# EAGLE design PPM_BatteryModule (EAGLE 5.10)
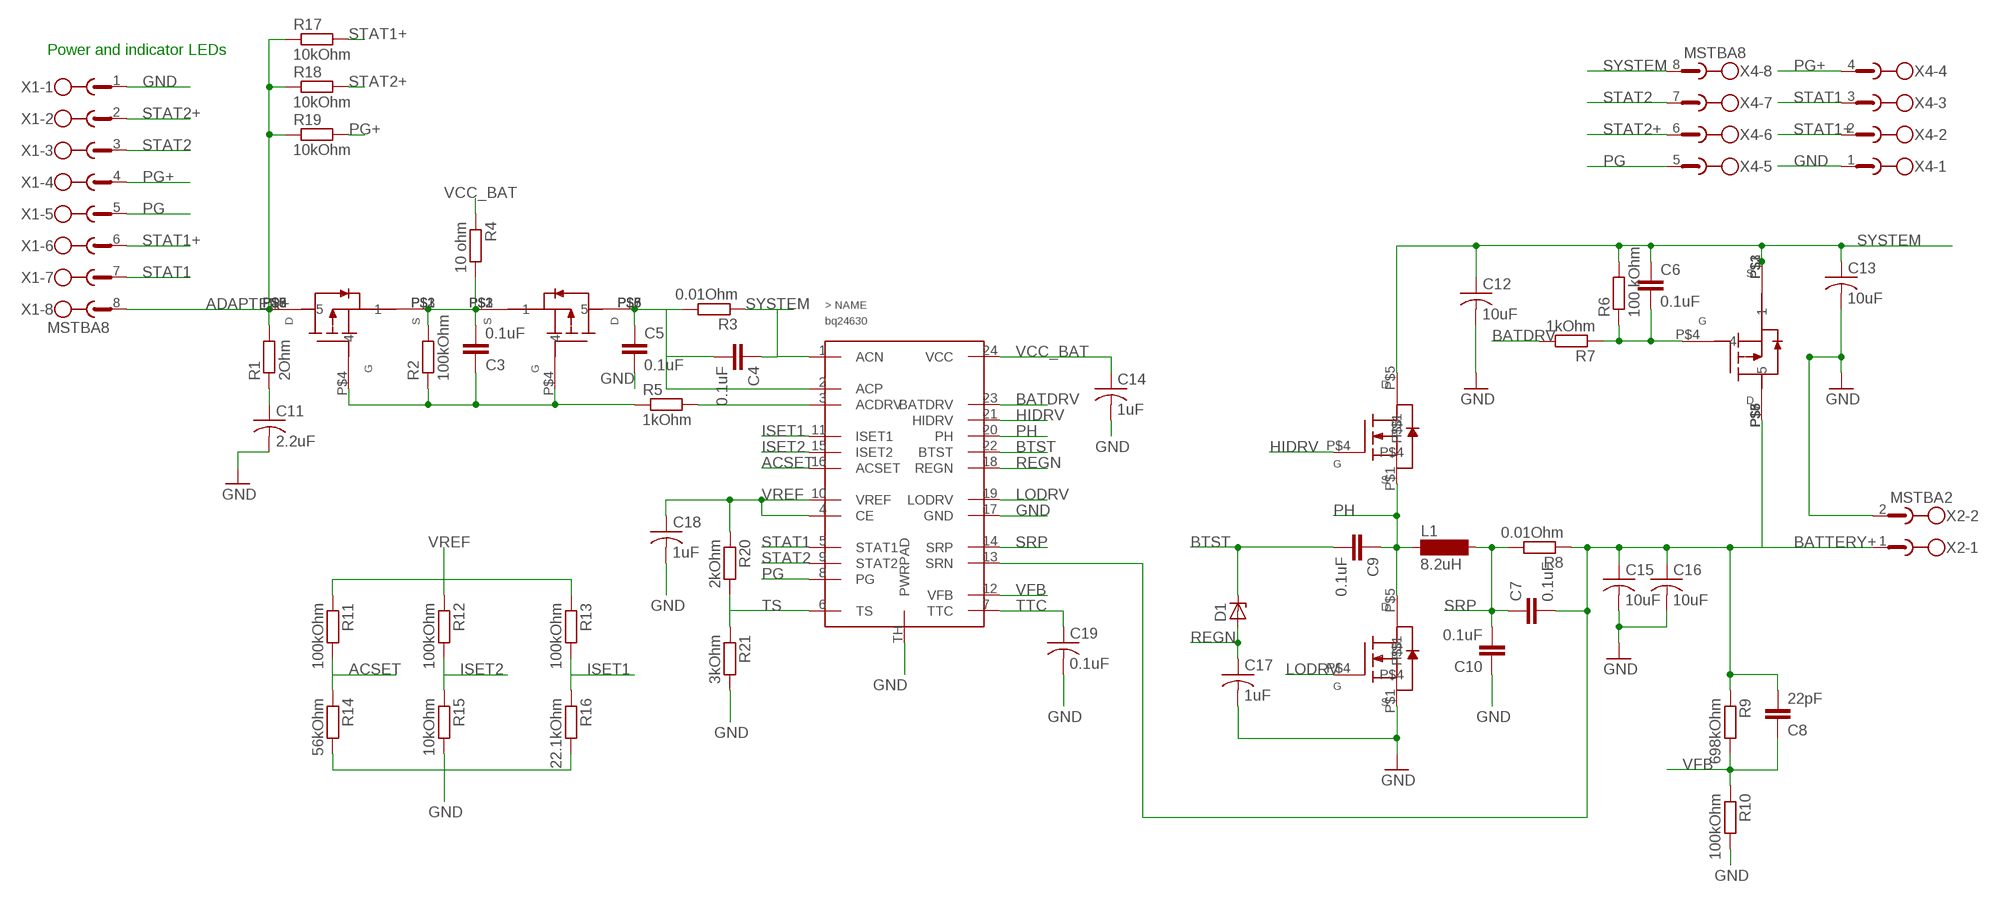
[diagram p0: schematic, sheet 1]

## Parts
C3  0.1uF  C-EUC1206  [C1206]
C4  0.1uF  C-EUC1206  [C1206]
C5  0.1uF  C-EUC1206  [C1206]
C6  0.1uF  C-EUC1206  [C1206]
C7  0.1uF  C-EUC1206  [C1206]
C8  22pF  C-EUC1206  [C1206]
C9  0.1uF  C-EUC1206  [C1206]
C10  0.1uF  C-EUC1206  [C1206]
C11  2.2uF  C-USC1206  [C1206]
C12  10uF  C-USC1206  [C1206]
C13  10uF  C-USC1206  [C1206]
C14  1uF  C-USC1206  [C1206]
C15  10uF  C-USC1206  [C1206]
C16  10uF  C-USC1206  [C1206]
C17  1uF  C-USC1206  [C1206]
C18  1uF  C-USC1206  [C1206]
C19  0.1uF  C-USC1206  [C1206]
D1  ZENER-DIODESOD80C  [SOD80C]
L1  8.2uH  SM-1206  [SM-1206]
Q1  SI7617DN  [POWERPAK1212-8]
Q2  SI7617DN  [POWERPAK1212-8]
Q3  SI7617DN  [POWERPAK1212-8]
Q4  SIS412DN  [POWERPAK1212-8]
Q5  SIS412DN  [POWERPAK1212-8]
R1  2Ohm  R-EU_M1206  [M1206]
R2  100kOhm  R-EU_M1206  [M1206]
R3  0.01Ohm  R-EU_M1206  [M1206]
R4  10 ohm  R-EU_M1206  [M1206]
R5  1kOhm  R-EU_M1206  [M1206]
R6  100 kOhm  R-EU_M1206  [M1206]
R7  1kOhm  R-EU_M1206  [M1206]
R8  0.01Ohm  R-EU_M1206  [M1206]
R9  698kOhm  R-EU_M1206  [M1206]
R10  100kOhm  R-EU_M1206  [M1206]
R11  100kOhm  R-EU_M1206  [M1206]
R12  100kOhm  R-EU_M1206  [M1206]
R13  100kOhm  R-EU_M1206  [M1206]
R14  56kOhm  R-EU_M1206  [M1206]
R15  10kOhm  R-EU_M1206  [M1206]
R16  22.1kOhm  R-EU_M1206  [M1206]
R17  10kOhm  R-EU_M1206  [M1206]
R18  10kOhm  R-EU_M1206  [M1206]
R19  10kOhm  R-EU_M1206  [M1206]
R20  2kOhm  R-EU_M1206  [M1206]
R21  3kOhm  R-EU_M1206  [M1206]
U$1  BQ24630  [QFN16]
X1  MSTBA8  [MSTBA8]
X2  MSTBA2  [MSTBA2]
X4  MSTBA8  [MSTBA8]

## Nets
ACP: C4.2 C5.1 Q2.P$5 Q2.P$6 Q2.P$7 Q2.P$8 R3.2 U$1.2(ACP)
ACSET: R11.2 R14.1 U$1.16(ACSET)
ADAPTER+: Q1.P$5 Q1.P$6 Q1.P$7 Q1.P$8 R1.2 R17.1 R18.1 R19.1 X1.8
BATDRV: R7.2 U$1.23(BATDRV)
BATTERY+: C7.2 C8.2 C15.1 C16.1 Q3.P$5 R8.1 R9.1 U$1.13(SRN) X2.1
BTST: C9.2 D1.C U$1.22(BTST)
GND: C5.2 C10.1 C11.2 C12.2 C13.2 C14.2 C15.2 C16.2 C17.2 C18.2 C19.2 Q5.P$1 R10.2 R14.2 R15.2 R16.2 R21.2 U$1.17(GND) U$1.TH(PWRPAD) X1.1 X2.2 X4.1
HIDRV: Q4.P$4 U$1.21(HIDRV)
ISET1: R13.2 R16.1 U$1.11(ISET1)
ISET2: R12.2 R15.1 U$1.15(ISET2)
LODRV: Q5.P$4 U$1.19(LODRV)
N$2: C3.2 Q1.P$1 Q1.P$2 Q1.P$3 Q2.P$1 Q2.P$2 Q2.P$3 R2.2 R4.2
N$6: C11.1 R1.1
N$7: C3.1 Q1.P$4 Q2.P$4 R2.1 R5.1
N$8: R5.2 U$1.3(ACDRV)
N$10: C6.2 Q3.P$4 R6.1 R7.1
PG: U$1.8(PG) X1.5 X4.5
PG+: R19.2 X1.4 X4.4
PH: C9.1 L1.1 Q4.P$1 Q5.P$5 U$1.20(PH)
REGN: C17.1 D1.A U$1.18(REGN)
SRP: C7.1 C10.2 L1.2 R8.2 U$1.14(SRP)
STAT1: U$1.5(STAT1) X1.7 X4.3
STAT1+: R17.2 X1.6 X4.2
STAT2: U$1.9(STAT2) X1.3 X4.7
STAT2+: R18.2 X1.2 X4.6
SYSTEM: C4.1 C6.1 C12.1 C13.1 Q3.P$1 Q3.P$2 Q3.P$3 Q4.P$5 R3.1 R6.2 U$1.1(ACN) X4.8
TS: R20.2 R21.1 U$1.6(TS)
TTC: C19.1 U$1.7(TTC)
VCC_BAT: C14.1 R4.1 U$1.24(VCC)
VFB: C8.1 R9.2 R10.1 U$1.12(VFB)
VREF: C18.1 R11.1 R12.1 R13.1 R20.1 U$1.4(CE) U$1.10(VREF)
Unconnected: Q3.P$6 Q3.P$7 Q3.P$8 Q4.P$2 Q4.P$3 Q4.P$6 Q4.P$7 Q4.P$8 Q5.P$2 Q5.P$3 Q5.P$6 Q5.P$7 Q5.P$8

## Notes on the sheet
- Power and indicator LEDs

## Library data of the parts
C3-C10 = rcl:C-EU: CAPACITOR, European symbol
C11-C19 = rcl:C-US: CAPACITOR, American symbol
D1 = diode:ZENER-DIODE: Z-Diode
L1 = inductor-neosid:SM-1206: INDUCTOR
Q1-Q3 = Oma:SI7617DN
Q4 Q5 = Oma:SIS412DN
R1-R21 = rcl:R-EU_: RESISTOR, European symbol
U$1 = Oma:BQ24630
X1 X4 = con-phoenix-508:MSTBA8: PHOENIX
X2 = con-phoenix-508:MSTBA2: PHOENIX

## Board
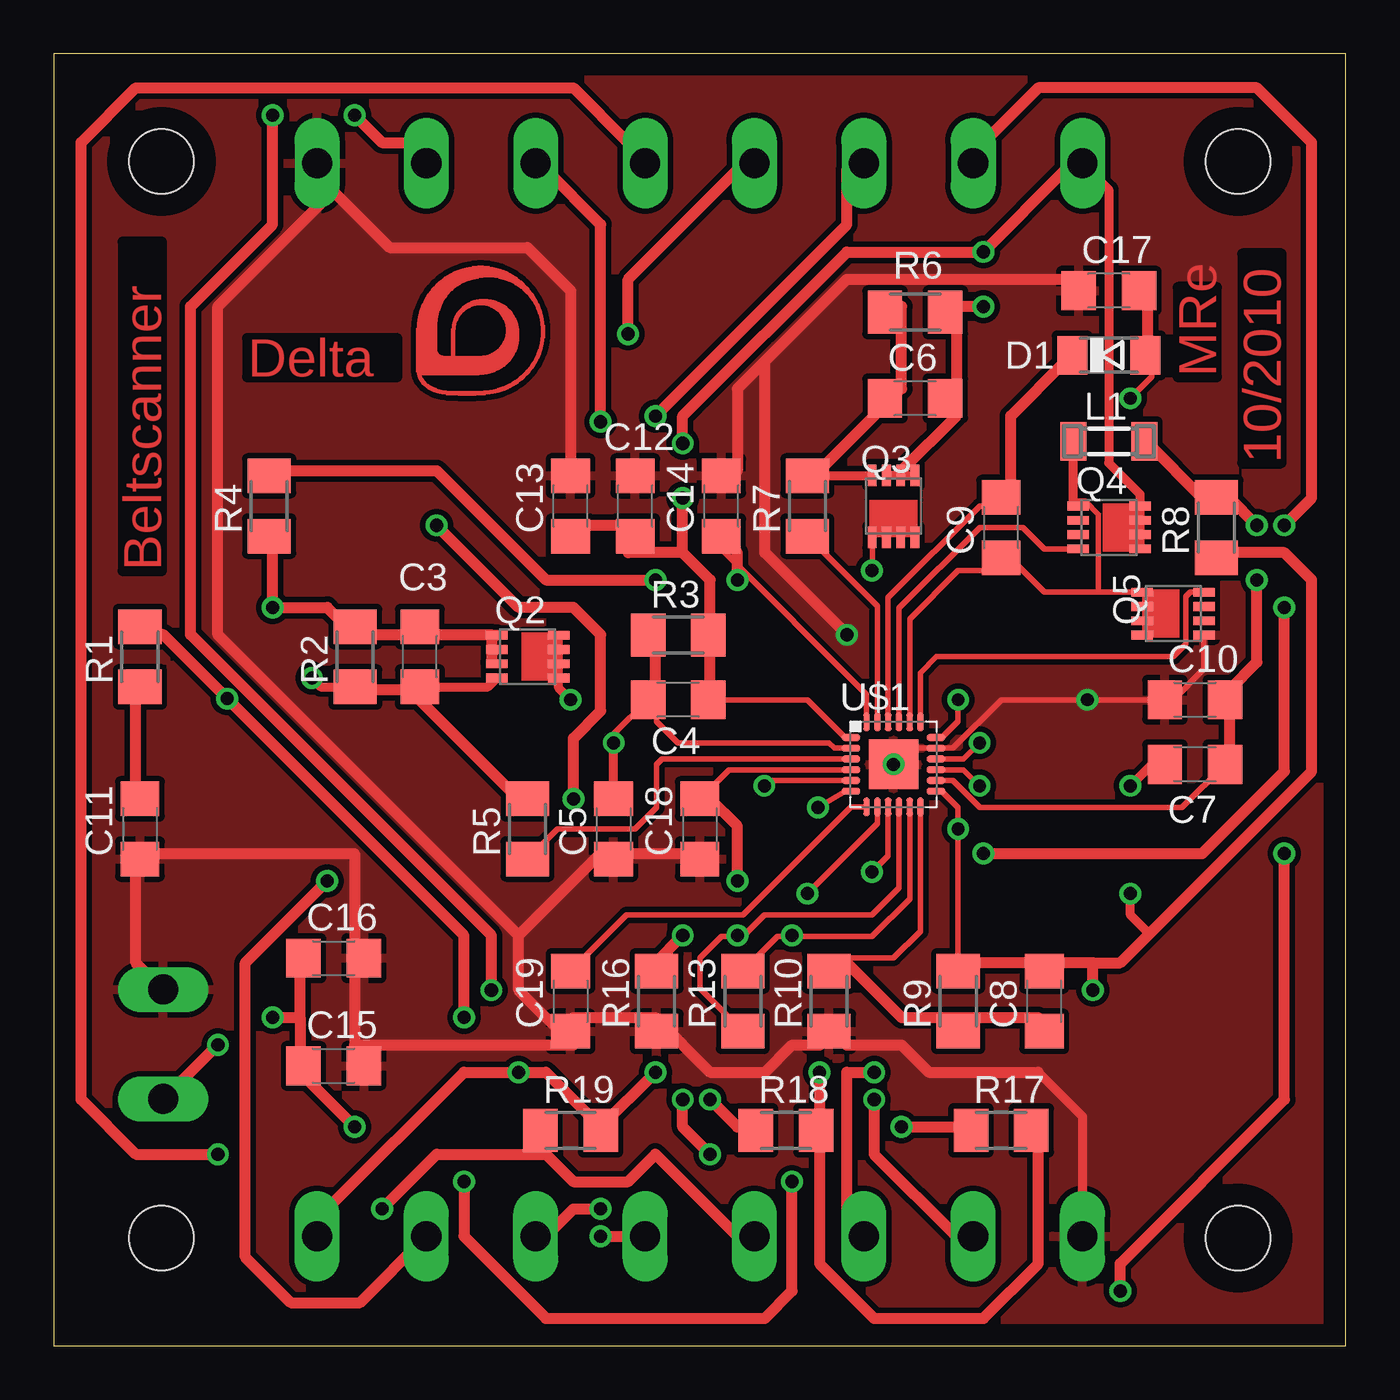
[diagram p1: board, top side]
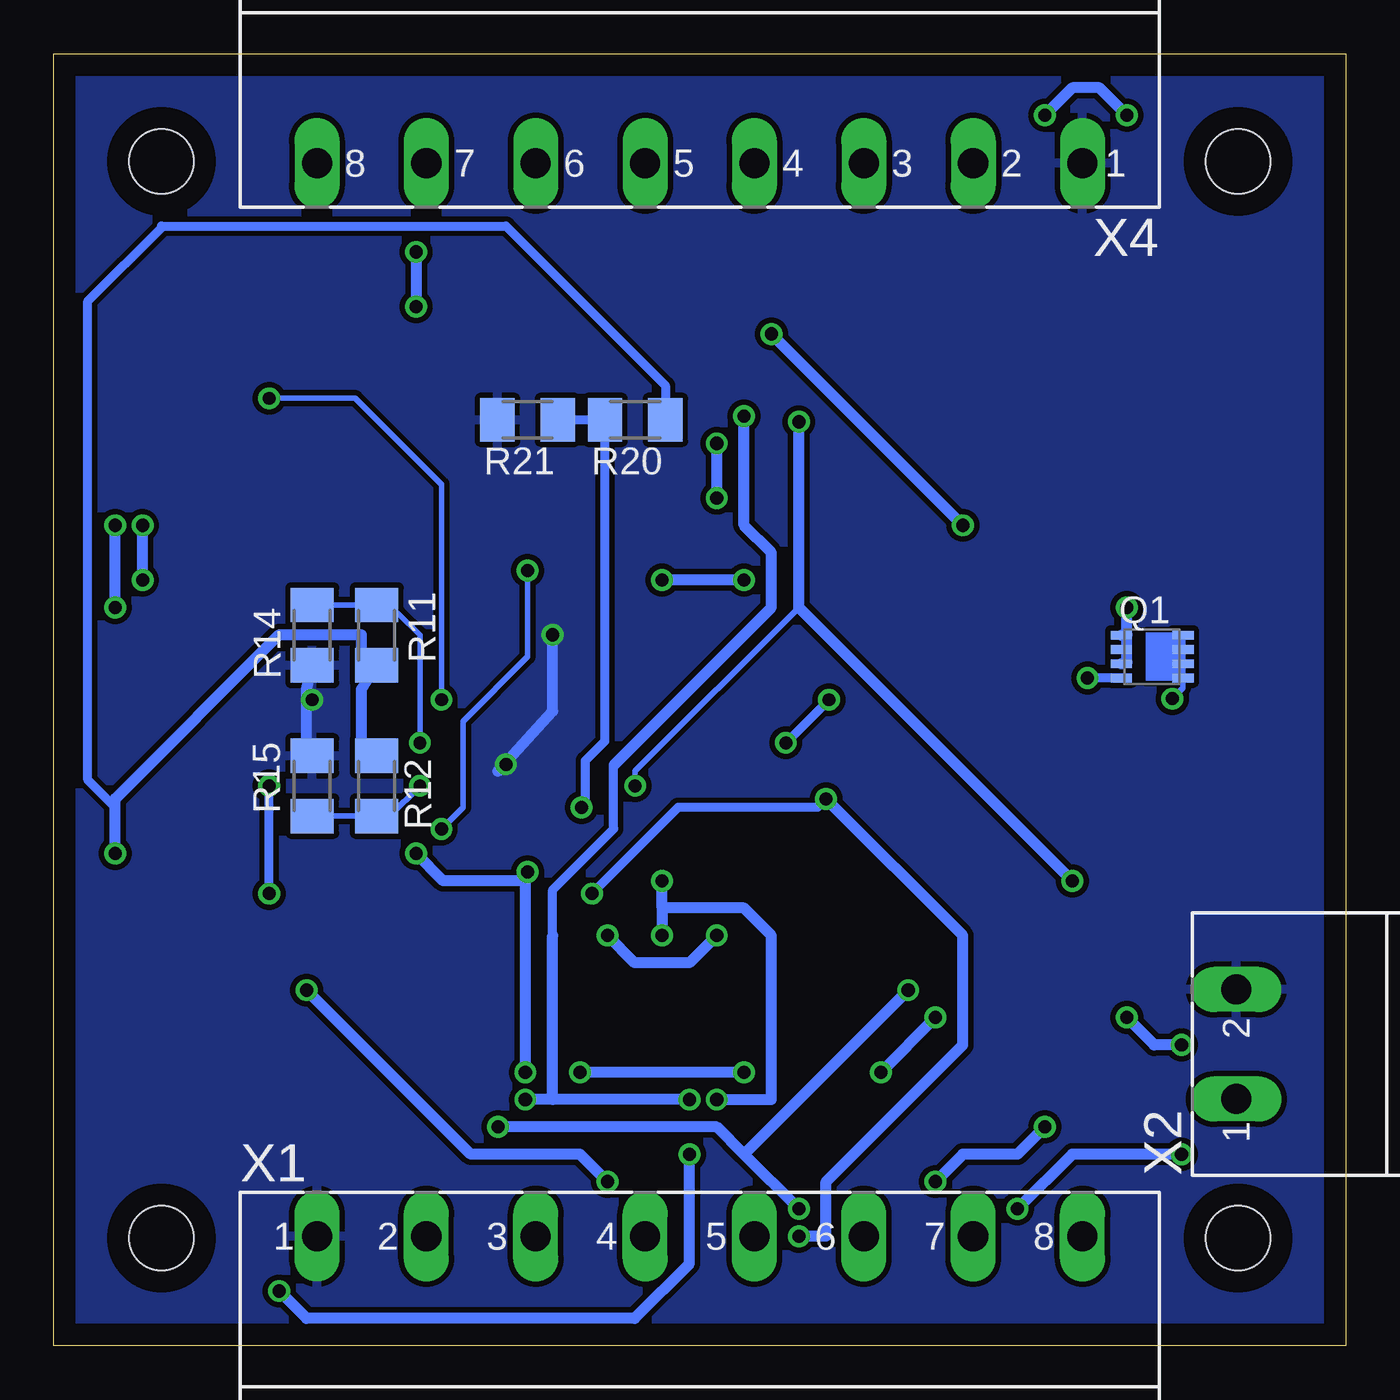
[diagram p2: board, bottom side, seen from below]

Size 60 x 60 mm. Coordinates in mm from the lower left corner, seen from the top.
Outline: 0,0 60,0 60,60 0,60 0,0
Copper layers (1*16): Top 0.035mm / dielectric 1.5mm / Bottom 0.035mm
Design rules "default *": minimum track width 20mil, minimum drill 24mil, track to track 10mil, track to pad 10mil, pad to pad 10mil, via to via 10mil, smd to smd 10mil, copper to edge 40mil, drill to drill 8mil, minimum pad ring 10mil, minimum via ring 8mil, stop-mask expansion 4mil, vias tented up to drill 0mil, thermal gap 10mil
Holes 3 mm at 5,55 55,55 55,5 5,5

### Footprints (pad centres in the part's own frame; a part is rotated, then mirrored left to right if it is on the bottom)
C1206 = smd 1.6 x 1.8: 1 -1.4,0; 2 1.4,0
SOD80C = smd 1.4 x 1.8: A 1.7,0; C -1.7,0
SM-1206 = smd 1.2 x 1.8: 1 -1.65,0; 2 1.65,0
POWERPAK1212-8 = smd 0.991 x 0.406: P$1 -1.422,0.991; P$2 -1.422,0.33; P$3 -1.422,-0.33; P$4 -1.422,-0.991; P$5 1.448,-0.991; P$6 1.448,-0.33; P$7 1.448,0.33; P$8 1.448,0.991
M1206 = smd 1.6 x 2: 1 -1.4,0; 2 1.4,0
QFN16 = smd 0.85 x 0.3: 1 -1.975,1.25; 2 -1.975,0.75; 3 -1.975,0.25; 4 -1.975,-0.25; 5 -1.975,-0.75; 6 -1.975,-1.25; 13 1.975,-1.25; 14 1.975,-0.75; 15 1.975,-0.25; 16 1.975,0.25; 17 1.975,0.75; 18 1.975,1.25 | smd 0.3 x 0.85: 7 -1.25,-1.975; 8 -0.75,-1.975; 9 -0.25,-1.975; 10 0.25,-1.975; 11 0.75,-1.975; 12 1.25,-1.975; 19 1.25,1.975; 20 0.75,1.975; 21 0.25,1.975; 22 -0.25,1.975; 23 -0.75,1.975; 24 -1.25,1.975 | smd 2.3 x 2.3: TH 0,0
MSTBA8 = drill 1.397 long: 1 -17.78,5.08; 2 -12.7,5.08; 3 -7.62,5.08; 4 -2.54,5.08; 5 2.54,5.08; 6 7.62,5.08; 7 12.7,5.08; 8 17.78,5.08
MSTBA2 = drill 1.397 long: 1 -2.54,5.08; 2 2.54,5.08

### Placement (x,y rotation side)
C3  17,32 90 top
C4  29,30 180 top
C5  26,24 270 top
C6  40,44 180 top
C7  53,27 180 top
C8  46,16 90 top
C9  44,38 90 top
C10  53,30 0 top
C11  4,24 270 top
C12  27,39 90 top
C13  24,39 90 top
C14  31,39 90 top
C15  13,13 0 top
C16  13,18 0 top
C17  49,49 180 top
C18  30,24 270 top
C19  24,16 270 top
D1  49,46 0 top
L1  49,42 0 top
Q1  9,32 0 bottom
Q2  22,32 0 top
Q3  39,39 270 top
Q4  49,38 0 top
Q5  52,34 180 top
R1  4,32 90 top
R2  14,32 90 top
R3  29,33 180 top
R4  10,39 270 top
R5  22,24 270 top
R6  40,48 0 top
R7  35,39 270 top
R8  54,38 90 top
R9  42,16 270 top
R10  36,16 270 top
R11  45,33 90 bottom
R12  45,26 270 bottom
R13  32,16 90 top
R14  48,33 270 bottom
R15  48,26 90 bottom
R16  28,16 270 top
R17  44,10 180 top
R18  34,10 180 top
R19  24,10 180 top
R20  33,43 180 bottom
R21  38,43 180 bottom
U$1  39,27 0 top
X1  30,0 0 bottom
X2  0,14 90 bottom
X4  30,60 180 bottom

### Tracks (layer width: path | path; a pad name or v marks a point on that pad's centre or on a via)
ACP  (via drill 0.6)
  Top 0.254: U$1.2 36.25,27.75 36,28 29,28 28,29 28,29.6 C4.2 26,28.4 v26,28
  Top 0.406: Q2.P$8 Q2.P$7 Q2.P$6 Q2.P$5 23.45,30.55 v24,30 | C5.1 v26,28
  Top 0.508: R3.2 27.94,33.02 27.94,30.48 C4.2
  Bottom 0.406: v26,28 v24,30
ACSET  (via drill 0.6)
  Top 0.254: U$1.16 42.25,27.25 v43,28
  Bottom 0.254: v43,28 43,33 44,34 44.6,34 R11.2 R14.1
ADAPTER+  (via drill 0.6, 0.61)
  Top 0.508: 35.56,10.16 35.56,3.81 38.1,1.27 43.18,1.27 45.72,3.81 45.72,10.16 R17.1 | v19.05,15.24 19.05,19.05 v8.05,30.05 5.08,33.02 3.81,33.02 R1.2 | 25.4,10.16 22.86,12.7 v21.59,12.7 19.05,12.7 12.7,6.35 12.7,5.08 X1.8 | v35.56,12.7 35.56,10.16 | 25.4,10.16 v27.94,12.7 | 35.56,10.16 R18.1 | 25.4,10.16 R19.1
  Bottom 0.254: Q1.P$5 Q1.P$6 Q1.P$7 Q1.P$8 7.55,30.55 v8.05,30.05
  Bottom 0.508: v21.59,12.7 v19.05,15.24 | v27.94,12.7 v35.56,12.7
BATDRV
  Top 0.254: U$1.23 38.25,34.35 R7.2
BATTERY+  (via drill 0.6, 0.61)
  Top 0.254: U$1.13 41.25,25.75 42,25 v42,24 R9.1 | Q3.P$5 v38.01,36.01 v38,36
  Top 0.406: C7.2 51,27 v50,26 | v50,21 50,20 50.88,19.12
  Top 0.508: 11.43,15.24 11.43,17.78 C16.1 | 11.43,15.24 11.43,12.7 | v10.16,15.24 11.43,15.24 | v7.62,13.97 5.08,11.43 X2.1 | 45.72,17.78 41.91,17.78 R9.1 | 48.26,17.78 45.72,17.78 | 48.26,17.78 49.53,17.78 50.88,19.12 58.42,26.67 58.42,35.56 57.15,36.83 54.61,36.83 R8.1 | 45.72,17.78 C8.2 | 11.43,12.7 v13.97,10.16 | v19.05,7.62 19.05,5.08 22.86,1.27 33.02,1.27 34.29,2.54 v34.29,7.62 | v48.26,16.51 48.26,17.78 | 11.43,12.7 C15.1
  Bottom 0.254: v38,36 38,32 41,29 41,25 v42,24
  Bottom 0.406: v50,21 v50,26
  Bottom 0.508: v10.16,15.24 8.89,13.97 v7.62,13.97 | v13.97,10.16 15.24,8.89 17.78,8.89 v19.05,7.62 | v34.29,7.62 35.56,8.89 40.64,8.89 v48.26,16.51
BTST
  Top 0.254: U$1.22 38.75,34.75 43,39 43.6,39 C9.2
  Top 0.508: D1.C 46.99,45.72 44.45,43.18 44.45,39.37 C9.2
GND  (via drill 0.6, 0.61)
  Top 0.254: U$1.TH 39.75,27.75 U$1.17 41.75,27.75 44,30 v48,30 C10.1 52,30 53.42,31.42 Q5.P$1
  Top 0.406: X1.1 47.78,10.64 45.72,12.7
  Top 0.508: 33.02,45.72 31.75,44.45 31.75,40.64 C14.2 | 33.02,45.72 36.83,49.53 46.99,49.53 C17.2 | v36.83,33.02 33.02,36.83 33.02,45.72 | 3.81,22.86 3.81,17.78 5.08,16.51 X2.2 | 13.97,17.78 13.97,13.97 | 13.97,13.97 13.97,12.7 C15.2 | C18.2 29.21,22.86 26.67,22.86 C5.2 25.4,22.86 21.59,19.05 | 27.94,15.24 24.13,15.24 C19.2 24.13,13.97 | 27.94,15.24 30.48,12.7 33.02,12.7 34.29,13.97 35.56,13.97 R10.2 36.83,13.97 39.37,13.97 40.64,12.7 45.72,12.7 | 27.94,15.24 R16.2 | 21.59,19.05 21.59,16.51 24.13,13.97 | 13.97,13.97 24.13,13.97 | 3.81,22.86 13.97,22.86 13.97,17.78 | 3.81,22.86 C11.2 | 13.97,17.78 C16.2 | 21.59,19.05 7.62,33.02 7.62,48.26 12.7,53.34 12.46,54.14 | 12.46,54.14 X4.1 | C13.2 24,49 22,51 15.6,51 12.46,54.14
  Bottom 0.406: 48.26,27.94 48.26,29.74 v48,30
  Bottom 0.508: v36.83,33.02 36.83,29.46 39.37,26.67 U$1.TH | R14.2 48.26,30.48 48.26,27.94 R15.2
  other vias: 39,27
  pour Top: 0,0 60,0 60,63 0,63
  pour Bottom: 0,60 60,60 60,-4 0,-4
HIDRV
  Top 0.254: U$1.21 39.25,34.25 43,38 45,38 46,37 47.57,37 Q4.P$4
ISET1  (via drill 0.61)
  Top 0.254: U$1.11 39.75,20.75 38,19 34.29,19 33.6,19 R13.2
  Top 0.508: v29.21,19.05 27.94,17.78 R16.1 | v34.29,19.05 34.29,19
  Bottom 0.508: v29.21,19.05 30.48,17.78 33.02,17.78 v34.29,19.05
ISET2  (via drill 0.6)
  Top 0.254: U$1.15 42.25,26.75 v43,26
  Bottom 0.254: R15.1 R12.2 44.4,24.6 v43,26
LODRV
  Top 0.254: U$1.19 40.25,31.25 41,32 52,32 52.58,32.58 52.58,34.8 52.78,35 Q5.P$4
N$2  (via drill 0.61)
  Top 0.305: 20.32,31.75 20.5,31.75 Q2.P$3
  Top 0.406: 20.32,31.75 20.32,32.07 Q2.P$2
  Top 0.508: R4.2 10.16,36.83 v10.16,34.29 12.7,34.29 13.97,33.02 | 20.32,33.02 20.32,31.75 | 20.32,33.02 17.78,33.02 C3.2 16.51,33.02 13.97,33.02 | 20.32,33.02 Q2.P$1 | 13.97,33.02 R2.2
  Bottom 0.254: 10.16,31.75 10.16,32.07 Q1.P$2
  Bottom 0.508: 10.16,33.02 10.16,31.75 Q1.P$3 | 10.16,33.02 v10.16,34.29 | 10.16,33.02 Q1.P$1
N$6
  Top 0.508: C11.1 3.81,25.4 3.81,30.48 R1.1
N$7  (via drill 0.6)
  Top 0.406: R2.1 12.4,30.6 v11.99,31.01 | C3.1 20.17,30.6 Q2.P$4
  Top 0.508: 16.51,30.48 13.97,30.48 R2.1 | 16.51,30.48 21.59,25.4 R5.1 | 16.51,30.48 C3.1
  Bottom 0.406: v12,31 v11.99,31.01 Q1.P$4
N$8
  Top 0.254: U$1.3 28.25,27.25 28,27 28,25 27,24 23.4,24 R5.2
N$10
  Top 0.406: Q3.P$4 35.02,40.42 R7.1
  Top 0.508: R7.1 35.56,40.64 38.1,43.18 C6.2 39.37,44.45 39.37,48.26 R6.1
PG  (via drill 0.6, 0.61)
  Top 0.254: U$1.8 38.25,24.25 v35,21
  Top 0.508: v24.13,25.4 24.13,28.21 25.4,29.48 25.4,33.02 24.13,34.29 21.59,34.29 v17.78,38.1 | v26.67,46.99 26.67,49.53 31.75,54.61 X4.5 | v25.4,5.08 X1.5
  Bottom 0.406: v35,21 31,25 24.53,25 v24.13,25.4
  Bottom 0.508: v25.4,5.08 24.13,5.08 24.13,7.62 17.78,13.97 17.78,19.05 v24.13,25.4 | v17.78,38.1 v26.67,46.99
PG+  (via drill 0.61)
  Top 0.508: 22.86,8.89 22.86,10.16 R19.2 | 22.86,8.89 24.13,7.62 26.67,7.62 27.94,8.89 31.75,5.08 X1.4 | v7.62,8.89 3.81,8.89 1.27,11.43 1.27,55.88 3.81,58.42 24.13,58.42 26.67,55.88 X4.4 | v15.24,6.35 17.78,8.89 22.86,8.89
  Bottom 0.508: v7.62,8.89 12.7,8.89 v15.24,6.35
PH
  Top 0.254: U$1.20 39.75,33.75 42,36 43.4,36 C9.1 44.4,36.6 46,35 48.51,35 | 48.51,35 Q5.P$5 | 47.35,39.22 47.9,39.22 48.51,38.61 48.51,35
  Top 0.406: L1.1 47.35,39.22 Q4.P$1
REGN  (via drill 0.6)
  Top 0.254: U$1.18 41.25,28.25 42,29 v42,30 | v50,44 51,45 51,45.7 D1.A
  Top 0.508: C17.1 50.8,48.26 50.8,45.72 D1.A
  Bottom 0.254: v42,30 42,40 46,44 v50,44
SRP  (via drill 0.61)
  Top 0.254: U$1.14 41.75,26.25 43,25 52.4,25 C7.1
  Top 0.508: C7.1 54.61,26.67 54.61,29.21 C10.2 54.61,30.48 55.88,31.75 v55.88,35.56 | L1.2 50.8,41.91 53.34,39.37 R8.2 54.61,39.37 v55.88,38.1
  Bottom 0.508: v55.88,35.56 v55.88,38.1
STAT1  (via drill 0.6, 0.61)
  Top 0.254: U$1.5 33.25,26.25 v33,26
  Top 0.508: v25.4,42.91 25.4,52.07 22.86,54.61 X4.3 | v12.7,21.59 8.89,17.78 8.89,4.11 11,2 14.22,2 X1.7
  Bottom 0.254: v33,26 33,26.69 25.4,34.29
  Bottom 0.508: v25.4,42.91 25.4,34.29 v12.7,21.59
STAT1+  (via drill 0.61)
  Top 0.508: v39.37,10.16 41.91,10.16 R17.2 | v25.4,6.35 24.13,6.35 22.86,5.08 X1.6 | v13.97,57.15 15.24,55.88 16.51,55.88 X4.2 | v10.16,57.15 10.16,52.07 6.35,48.26 6.35,33.02 20.32,19.05 v20.32,16.51
  Bottom 0.508: v39.37,10.16 29.21,10.16 27.94,8.89 | v25.4,6.35 27.94,8.89 | v13.97,57.15 12.7,58.42 11.43,58.42 v10.16,57.15 | 27.94,8.89 v20.32,16.51
STAT2  (via drill 0.6, 0.61)
  Top 0.254: U$1.9 38.75,22.75 v38,22
  Top 0.508: v38.1,12.7 36.83,12.7 36.83,5.08 X1.3 | v57.15,38.1 58.42,39.37 58.42,55.88 55.88,58.42 45.72,58.42 43.18,55.88 X4.7 | v57.15,34.29 57.15,26.67 53.34,22.86 v43.18,22.86
  Bottom 0.508: v38.1,12.7 38.1,21.59 | v57.15,34.29 v57.15,38.1 | v43.18,22.86 41.91,21.59 38.1,21.59 | 38.1,21.59 v38,22
STAT2+  (via drill 0.61)
  Top 0.508: v30.48,11.43 31.75,10.16 33.02,10.16 R18.2 | v38.1,11.43 38.1,8.89 41.91,5.08 X1.2 | v27.94,43.18 36.83,52.07 36.83,54.61 X4.6
  Bottom 0.406: 36.83,19.05 36.83,21.17 34,24 34,26.96 33.98,26.98
  Bottom 0.508: 36.83,11.43 v38.1,11.43 | v30.48,11.43 36.83,11.43 | v27.94,43.18 27.94,38.1 26.67,36.83 26.67,34.29 33.98,26.98 | 36.83,11.43 36.83,19.05
SYSTEM  (via drill 0.61)
  Top 0.254: U$1.1 36.75,28.25 35,30 C4.1
  Top 0.406: Q3.P$3 Q3.P$2 Q3.P$1 | Q4.P$5 50.45,39.55 49,41 49,53.7 X4.8
  Top 0.508: Q3.P$2 39.37,40.64 41.91,43.18 C6.1 41.91,44.45 41.91,48.26 | v43.18,48.26 41.91,48.26 | X4.8 46.99,54.61 v43.18,50.8 36.83,50.8 29.21,43.18 v29.21,41.91 | 41.91,48.26 R6.2 | 30.48,33.02 30.48,30.48 C4.1 | 30.48,33.02 30.48,35.56 29.21,36.83 | 29.21,36.83 26.67,36.83 C12.1 26.67,38.1 24.13,38.1 C13.1 | 30.48,33.02 R3.1 | 29.21,36.83 v29.21,39.37
  Bottom 0.508: v43.18,50.8 v43.18,48.26 | v29.21,39.37 v29.21,41.91
TS  (via drill 0.6)
  Top 0.254: U$1.6 36.75,25.75 v35.49,25
  Bottom 0.406: v35.49,25 35.31,25.19 35.31,27.18 34.4,28.08 R20.2 R21.1
TTC
  Top 0.254: U$1.7 37.02,25.02 32,20 26.6,20 C19.1
VCC_BAT  (via drill 0.61)
  Top 0.254: U$1.24 37.75,30.25 31,37 C14.1
  Top 0.508: v27.94,35.56 22.86,35.56 17.78,40.64 10.16,40.64 R4.1 | v31.75,35.56 31.75,36.83 C14.1
  Bottom 0.508: v27.94,35.56 v31.75,35.56
VFB
  Top 0.254: U$1.12 40.25,19.25 39,18 36.6,18 R10.1
  Top 0.508: 41.91,15.24 45.72,15.24 C8.1 | 41.91,15.24 39.37,15.24 36.83,17.78 R10.1 | 41.91,15.24 R9.2
VREF  (via drill 0.61)
  Top 0.254: U$1.10 39.25,21.25 38,20 33,20 32,19 31.75,19 31,19 30,18 30,16.6 R13.1 | U$1.4 31.35,26.75 C18.1
  Top 0.508: v31.75,21.59 31.75,24.13 30.48,25.4 C18.1 | v31.75,19.05 31.75,19 | v57.15,22.86 57.15,11.43 49.53,3.81 v49.53,2.54 | v30.48,8.89 29.21,10.16 v29.21,11.43
  Bottom 0.406: R20.1 31.6,44.6 39,52 55,52 55,51.93 58.42,48.51 58.42,26.27 57.15,25
  Bottom 0.508: 31.75,20.32 v31.75,19.05 | 31.75,20.32 v31.75,21.59 | R12.1 45.72,27.94 45.72,30.48 R11.1 45.72,31.75 45.72,33.02 49.53,33.02 57.15,25.4 57.15,25 v57.15,22.86 | v49.53,2.54 48.26,1.27 33.02,1.27 30.48,3.81 v30.48,8.89 | v29.21,11.43 26.67,11.43 26.67,19.05 27.94,20.32 31.75,20.32
(copper drawn outside any net)
  shapes: Top area x697

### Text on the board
Top: Delta | MRe | 10/2010 | Beltscanner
